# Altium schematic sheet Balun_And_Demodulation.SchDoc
size A4
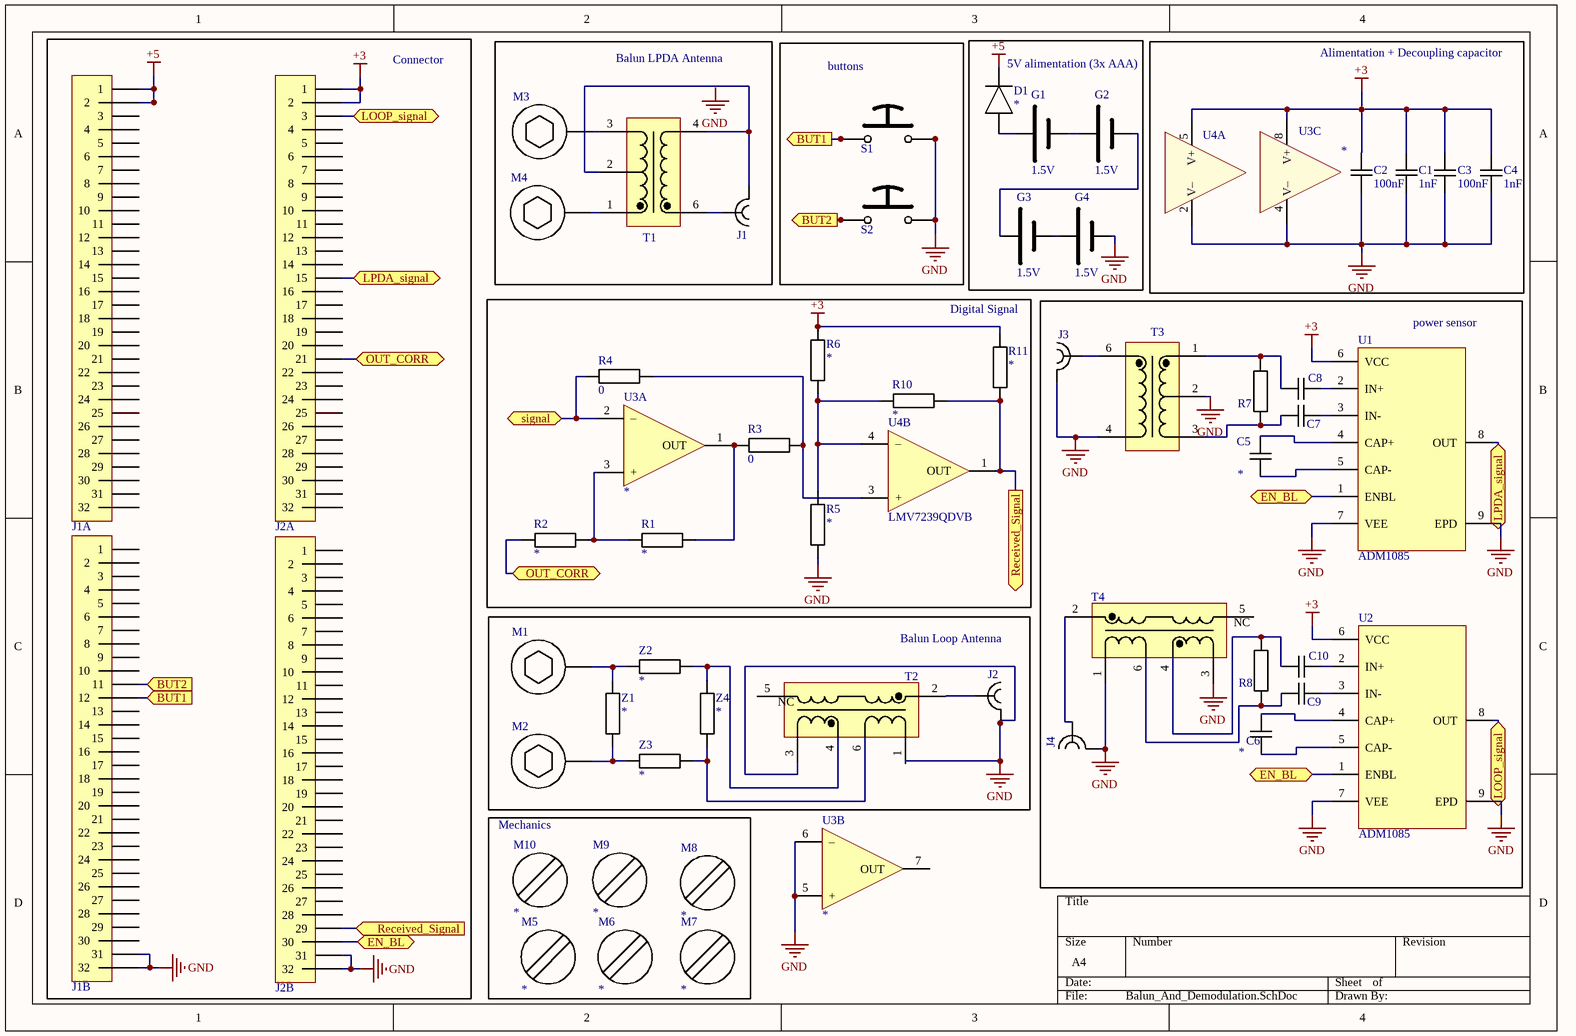
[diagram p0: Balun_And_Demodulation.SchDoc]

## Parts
C1  1nF  [CAPACITOR 2012 REFLOW]
C2  100nF  [CAPACITOR 2012 REFLOW]
C3  100nF  [CAPACITOR 2012 REFLOW]
C4  1nF  [CAPACITOR 2012 REFLOW]
C5  *  [CAPACITOR 2012 REFLOW]
C6  *  [CAPACITOR 2012 REFLOW]
C7  (no value)  [CAPACITOR 1005 REFLOW]
C8  (no value)  [CAPACITOR 1005 REFLOW]
C9  (no value)  [CAPACITOR 1005 REFLOW]
C10  (no value)  [CAPACITOR 1005 REFLOW]
D1  *  [DIODE DO35 P7.5]
G1  1.5V  [1.5V Cell AA/LR6]
G2  1.5V  [1.5V Cell AA/LR6]
G3  1.5V  [1.5V Cell AA/LR6]
G4  1.5V  [1.5V Cell AA/LR6]
J1  CONSMA001-G  [SMA TH Vertical Linx CONSMA001-G]  (value not drawn)
J1A  *  [PinHeader2x16 P2.54]  (value not drawn)
J1B  *  [PinHeader2x16 P2.54]  (value not drawn)
J2  CONSMA001-G  [SMA TH Vertical Linx CONSMA001-G]  (value not drawn)
J2A  *  [PinHeader2x16 P2.54]  (value not drawn)
J2B  *  [PinHeader2x16 P2.54]  (value not drawn)
J3  CONSMA001-G  [SMA TH Vertical Linx CONSMA001-G]  (value not drawn)
J4  CONSMA001-G  [SMA TH Vertical Linx CONSMA001-G]  (value not drawn)
M1  (no value)  [Screw Hex Socket M2.5X4 Connected]
M2  (no value)  [Screw Hex Socket M2.5X4 Connected]
M3  (no value)  [Screw Hex Socket M2.5X4 Connected]
M4  (no value)  [Screw Hex Socket M2.5X4 Connected]
M5  *  [Screw M3X12 Unconnected]
M6  *  [Screw M3X12 Unconnected]
M7  *  [Screw M3X12 Unconnected]
M8  *  [Screw M3X12 Unconnected]
M9  *  [Screw M3X12 Unconnected]
M10  *  [Screw M3X12 Unconnected]
R1  *  [RESISTOR 2012 REFLOW]
R2  *  [RESISTOR 2012 REFLOW]
R3  0  [RESISTOR 2012 REFLOW]
R4  0  [RESISTOR 2012 REFLOW]
R5  *  [RESISTOR 2012 REFLOW]
R6  *  [RESISTOR 2012 REFLOW]
R7  0  [RESISTOR 1005 REFLOW]  (value not drawn)
R8  0  [RESISTOR 1005 REFLOW]  (value not drawn)
R10  *  [RESISTOR 2012 REFLOW]
R11  *  [RESISTOR 2012 REFLOW]
S1  *  [Push Button C6.0x6.0 WE 430186130716]  (value not drawn)
S2  *  [Push Button C6.0x6.0 WE 430186130716]  (value not drawn)
T1  {Value}  [TC1-1TG2+]  (value not drawn)
T2  {Value}  [NCS2-771-75+]  (value not drawn)
T3  {Value}  [TC1-1TG2+]  (value not drawn)
T4  {Value}  [NCS2-771-75+]  (value not drawn)
U1  ADM1085  [DFN8 P0.5 T0.6X1.2 C2.0X3.0 H0.8]
U2  ADM1085  [DFN8 P0.5 T0.6X1.2 C2.0X3.0 H0.8]
U3  *  [DIP8 P2.54 W7.62 H5.0]  (parts A,B,C of 3)
U4  LMV7239QDVB  [SOT23-5 P0.95 C1.6x3.0 H1.3]  (value not drawn)  (parts A,B of 2)
Z1  *  [RESISTOR 2012 REFLOW]
Z2  *  [RESISTOR 2012 REFLOW]
Z3  *  [RESISTOR 2012 REFLOW]
Z4  *  [RESISTOR 2012 REFLOW]

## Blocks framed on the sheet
Connector: J1A J1B J2A J2B
Balun LPDA Antenna: J1 M3 M4 T1
buttons: S1 S2
5V alimentation (3x AAA): D1 G1-G4
Alimentation + Decoupling capacitor: C1-C4 U3 U4
Digital Signal: R1-R6 R10 R11 U3 U4
power sensor: C5-C10 J3 J4 R7 R8 T3 T4 U1 U2
Balun Loop Antenna: J2 M1 M2 T2 Z1-Z4
Mechanics: M5-M10

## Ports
BUT1 (in), BUT1 (out), BUT2 (in), BUT2 (out), EN_BL (bidir), LOOP_signal (bidir), LPDA_signal (bidir), OUT_CORR (bidir), Received_Signal (in), Received_Signal (out), signal (bidir)

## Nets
+3: C1.2 C2.2 C3.2 C4.2 J2A.1 J2A.2 R6.1 R11.2 U1.6(VCC) U2.6(VCC) U3.8(V+) U4.5(V+)
+5: D1.1(C) J1A.1 J1A.2
GND: C1.1 C2.1 C3.1 C4.1 G4.2(—) J1B.31 J1B.32 J2.2 J2B.31 J2B.32 J3.2 J4.2 R5.2 S1.3 S1.4 S2.3 S2.4 T2.1 T2.3 T3.2 T3.4 T4.1 T4.3 U1.7(VEE) U1.9(EPD) U2.7(VEE) U2.9(EPD) U3.4(V–) U3.5(+) U3.6(–) U4.2(V–)
BUT1: J1B.12 S1.1 S1.2 ; port BUT1
BUT2: J1B.11 S2.1 S2.2 ; port BUT2
EN_BL: J2B.30 U1.1(ENBL) U2.1(ENBL) ; port EN_BL
LOOP_signal: J2A.3 U2.8(OUT) ; port LOOP_signal
LPDA_signal: J2A.15 U1.8(OUT) ; port LPDA_signal
OUT_CORR: J2A.21 R2.2 ; port OUT_CORR
Received_Signal: J2B.29 R10.2 R11.1 U4.1(OUT) ; port Received_Signal
signal: R4.2 U3.2(–) ; port signal
NetC5_1: C5.1 U1.5(CAP-)
NetC5_2: C5.2 U1.4(CAP+)
NetC6_1: C6.1 U2.5(CAP-)
NetC6_2: C6.2 U2.4(CAP+)
NetC7_1: C7.1 U1.3(IN-)
NetC7_2: C7.2 R7.2 T3.3
NetC8_1: C8.1 U1.2(IN+)
NetC8_2: C8.2 R7.1 T3.1
NetC9_1: C9.1 U2.3(IN-)
NetC9_2: C9.2 R8.2 T4.6
NetC10_1: C10.1 U2.2(IN+)
NetC10_2: C10.2 R8.1 T4.4
NetD1_2: D1.2(A) G1.1(+)
NetG1_2: G1.2(—) G2.1(+)
NetG2_2: G2.2(—) G3.1(+)
NetG3_2: G3.2(—) G4.1(+)
NetJ1_1: J1.1 T1.6
NetJ1_2: J1.2 T1.2 T1.4
NetJ2_1: J2.1 T2.2
NetJ3_1: J3.1 T3.6
NetJ4_1: J4.1 T4.2
NetM1_1: M1.1 Z1.2 Z2.1
NetM2_1: M2.1 Z1.1 Z3.1
NetM3_1: M3.1 T1.3
NetM4_1: M4.1 T1.1
NetR1_1: R1.1 R3.2 U3.1(OUT)
NetR1_2: R1.2 R2.1 U3.3(+)
NetR3_1: R3.1 R4.1 U4.3(+)
NetR5_1: R5.1 R6.2 R10.1 U4.4(–)
NetT2_4: T2.4 Z2.2 Z4.2
NetT2_6: T2.6 Z3.2 Z4.1

Not connected (* = marked no-connect by the designer): J1A 3 4 5 6 7 8 9 10 11 12 13 14 15 16 17 18 19 20 21 22 23 24 25 26 27 28 29 30 31 32; J1B 1 2 3 4 5 6 7 8 9 10 13 14 15 16 17 18 19 20 21 22 23 24 25 26 27 28 29 30; J2A 4 5 6 7 8 9 10 11 12 13 14 16 17 18 19 20 22 23 24 25 26 27 28 29 30 31 32; J2B 1 2 3 4 5 6 7 8 9 10 11 12 13 14 15 16 17 18 19 20 21 22 23 24 25 26 27 28; T2 5; T4 5; U3 7(OUT)

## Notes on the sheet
- Labels drawn without touching a wire or pin: GND

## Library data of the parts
C1-C10 = Capacitor
D1 = DIODE: Diode generic 2 leads
G1-G4 = Battery: Battery Generic
J1-J4 = SMA TH VERTICAL LINX CONSMA001-G
J1A J1B J2A J2B = PinHeader2x16: Plug connector
M1-M4 = Screw Hex Socket Connected: Screw Hex Socket Connected BN610
M5-M10 = Screw Unconnected: Screw Unconnected BN330
R1-R8 R10 R11 Z1-Z4 = Resistor
S1 S2 = Push Button 4Pins: Push Button, 4 pins, 2 poles parrallèle; pin to pad: 2>3 3>2
T1 T3 = TC1-1TG2+: Mini-Circuits RF Transformer
T2 T4 = NCS2-771-75+: Mini-Circuits RF Transformer
U1 U2 = LT5537: Wide Dynamic Range RF/IF Log Detector
U3 = OPA DUAL: Generic dual OPA 8 pins
U4 = COMPARATOR SINGLE SOT23-5: Generic Single Comparator 5pins 1OUT/2-V/3+IN/4-IN/5+V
